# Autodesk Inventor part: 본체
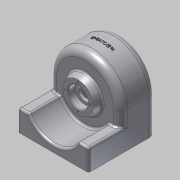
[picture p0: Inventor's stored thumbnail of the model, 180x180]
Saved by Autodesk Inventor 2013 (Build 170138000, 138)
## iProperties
Created: 2015-02
Part Number: 본체
Material: 알루미늄 6061
Document SubType Name: Modeling
Designer: Administrator
Density: 1 g/cm^3
Author: Administrator
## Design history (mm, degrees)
sketch "스케치1"
  geometry: L1 (-50, -50)-(50, -50); L2 (50, -50)-(50, 50); L3 (50, 50)-(-50, 50); L4 (-50, 50)-(-50, -50); L5 (-50, -50)-(50, 50); L6 (50, -50)-(-50, 50); 1 further point
  constraints: 12 end point, 2 midpoint, 2 parallel, 1 horizontal, 1 perpendicular
  dimensions: "d0" = 100 distance of L3.end L2.end; "d1" = 100 distance of L2.end L1.end
extrude "돌출1" new body sketch "스케치1" distance "d2" = 50; taper "d3" = 0 deg
fillet "모깎기1" dims "d4" = 50
feature "쉘1" dims "d5" = 4
sketch "스케치2"
  geometry: C1 r 25 at (0, 0); A1 r 50 centre (0, 0) between (50, 0) and (-50, 0) reference
  constraints: 1 centre point, 1 coincident
  dimensions: "d6" = 50 diameter of C1
extrude "돌출2" join sketch "스케치2" distance "d7" = 10; taper "d8" = -20 deg
hole "구멍1" diameter "d11" = 20; stored, may be unused: countersink angle "d15" = 90 deg, drill point angle "d17" = 0 deg; dims "d9" = 10, "d10" = 10, "d12" = 6, "d13" = 28, "d14" = 10, "d16" = 4
sketch "스케치3"
  geometry: C1 r 20 at (0, 0); A1 r 50 centre (0, 0) between (50, 0) and (-50, 0) reference
  constraints: 1 centre point, 1 coincident
  dimensions: "d18" = 40 diameter of C1
extrude "돌출3" join sketch "스케치3" distance "d19" = 9; taper "d20" = 0 deg
hole "구멍2" diameter "d23" = 20; stored, may be unused: countersink angle "d27" = 90 deg, drill point angle "d29" = 0 deg; dims "d21" = 10, "d22" = 10, "d24" = 6, "d25" = 28, "d26" = 8, "d28" = 2
sketch "스케치4"
  geometry: L1 (-50, 0)-(-50, -50) reference; L2 (-50, -50)-(50, -50) reference; L3 (50, -50)-(50, 0) reference; L4 (-50, -50)-(50, -50); L5 (50, -20)-(34.641, -20); L6 (-50, -50)-(-50, -20); L7 (-50, -20)-(-34.641, -20); L8 (50, -50)-(50, -20); A1 r 50 centre (0, 0) between (50, 0) and (-50, 0) reference; A2 r 40 centre (0, 0) between (-34.641, -20) and (34.641, -20)
  constraints: 10 end point, 3 collinear, 2 point on circle, 2 point on line, 1 centre point, 1 coincident, 1 parallel, 1 perpendicular
  dimensions: "d30" = 40 radius of A2; "d31" = 30 distance between parallel lines of L2 L5
extrude "돌출4" join sketch "스케치4" distance "d32" = 45; taper "d33" = 0 deg
fillet "모깎기2" dims "d34" = 10, "d35" = 6
fillet "모깎기3" dims "d36" = 0.3, "d37" = 3
chamfer "모따기1" distance "d38" = 1; stored, may be unused: second distance "d39" = 2, angle "d40" = 45 deg
fillet "모깎기4" dims "d41" = 3
sketch "스케치5" dims "d42" = 36
  geometry: C1 r 15 at (0, 0) reference; 2 further points
  constraints: 2 vertical alignment, 1 coincident, 2 other
hole "구멍3" sketch "스케치5" at (0, 18) diameter "d43" = 2.459; stored, may be unused: countersink angle "d47" = 90 deg, drill point angle "d49" = 118 deg; dims "d44" = 6, "d45" = 4, "d46" = 2, "d48" = 9
sketch "스케치6"
  geometry: L1 (90, 10)-(90, 92) reference; L2 (-7, 95)-(87, 95) reference; 2 further points
  dimensions: "d53" = 9 distance from line of L2 point (81.75, 86); "d54" = 8.25 distance from line of L1 point (81.75, 86)
hole "구멍4" sketch "스케치6" at (81.75, 86) diameter "d55" = 5.134; stored, may be unused: countersink angle "d59" = 90 deg, drill point angle "d61" = 118 deg; dims "d56" = 10, "d57" = 4, "d58" = 2, "d60" = 13
node "작업 평면1"
sketch "스케치7"
  geometry: L1 (40, 0)-(-40, 0) reference; 3 further points
  constraints: 1 midpoint, 1 vertical alignment, 1 other
  dimensions: "d68" = 25 distance from line of point (0, 25) L1
feature "엠보싱1" sketch "스케치7" dims "d0" = 100, "d1" = 100, "d11" = 20, "d69" = 0.5, "d70" = 0
node "솔리드1"
pattern_circular "원형 패턴1" dims angle "d51" = 360 deg
pattern_linear "직사각형 패턴1" dims "d64" = 33, "d67" = 83.5
